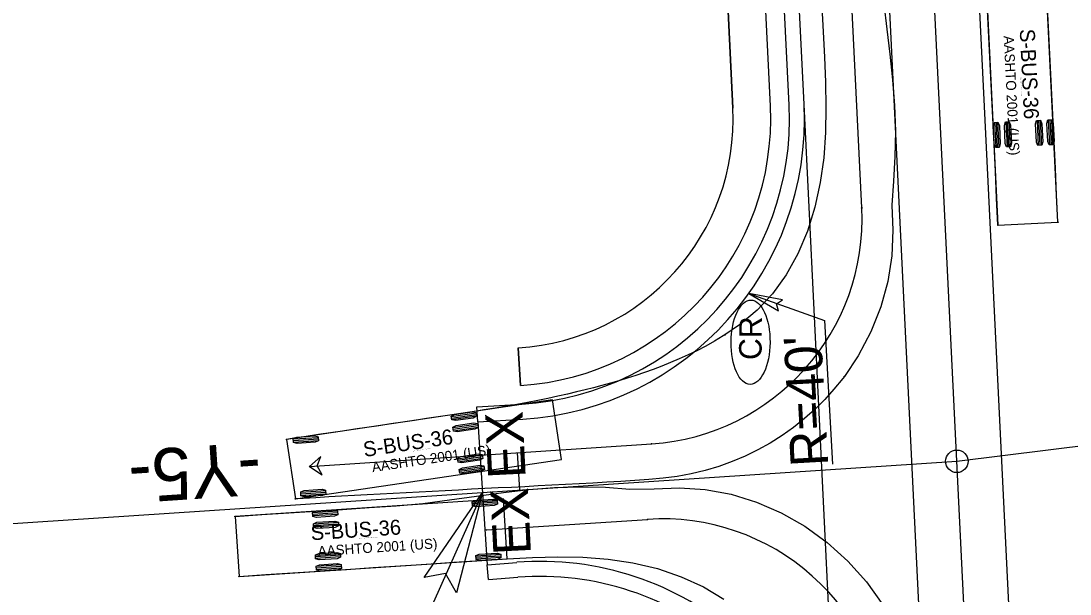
# Model space of a CAD drawing. Extents: x 2367848 to 2369479, y 800728 to 808616.
# Drawn here: x 2368698.2 to 2368837.9, y 804048.8 to 804125 of the extents above; entities that cross this region are included whole.
import ezdxf

# ---------------------------------------------------------------- set-up
doc = ezdxf.new("R2010")
doc.units = 0
for name, color, linetype in [('Prop AutoTurn Projected Path', 7, 'Continuous'), ('Prop AutoTurn Simulation', 7, 'Continuous'), ('Prop Conc 2ft 6in Curb and Gutter', 7, 'Continuous'), ('Prop Conc 4in Sidewalk', 7, 'Continuous'), ('Prop Dimension', 7, 'Continuous'), ('Prop EOT', 7, 'Continuous'), ('Prop Horizontal Alignment', 7, 'Continuous'), ('Prop Horizontal Alignment Station Label', 7, 'Continuous'), ('Prop Horizontal Alignment Tick Small', 7, 'Continuous'), ('Prop Lane Lines', 7, 'Continuous'), ('Prop Shade Light', 7, 'Continuous'), ('Prop Terminator CELL', 7, 'Continuous'), ('Prop WCC CELL', 7, 'Continuous'), ('Prop WCR CELL', 7, 'Continuous')]:
    doc.layers.add(name, color=color, linetype=linetype)

# ---------------------------------------------------------------- blocks, each defined once
blk = doc.blocks.new('CR')
at = {"layer": 'Prop WCC CELL'}
blk.add_ellipse((0.02, -0.02), major_axis=(5.61, 0), ratio=0.462467, dxfattribs=at)
blk.add_text('CR', height=3, dxfattribs=at).set_placement((-2.34, -1.5))

msp = doc.modelspace()

# ---------------------------------------------------------------- linework, layer by layer
at = {"layer": 'Prop AutoTurn Projected Path'}
for p, q in [((2368810.14, 804100.16), (2368808.54, 804132.96)), ((2368736.6, 804065.76), (2368782.15, 804068.76)), ((2368760.18, 804057.29), (2368781.62, 804058.7))]:
    msp.add_line(p, q, dxfattribs=at)
for centre, start, end in [((2368780.18, 804098.7), 273.7692, 2.7965), ((2368783.59, 804028.77), 2.7965, 93.7692)]:
    msp.add_arc(centre, 30, start, end, dxfattribs=at)
at = {"layer": 'Prop AutoTurn Simulation'}
for p, q in [((2368836.27, 804098.26), (2368834.52, 804134.02)), ((2368826.53, 804133.63), (2368828.28, 804097.87)), ((2368827.82, 804111.53), (2368827.98, 804108.2)), ((2368828.02, 804111.54), (2368828.19, 804108.21)), ((2368828.23, 804111.55), (2368828.4, 804108.22)), ((2368829.31, 804111.6), (2368829.48, 804108.28)), ((2368829.52, 804111.61), (2368829.69, 804108.29)), ((2368829.73, 804111.62), (2368829.89, 804108.3)), ((2368833.48, 804111.81), (2368833.64, 804108.48)), ((2368833.68, 804111.82), (2368833.85, 804108.49)), ((2368833.89, 804111.83), (2368834.06, 804108.5)), ((2368834.97, 804111.88), (2368835.14, 804108.55)), ((2368835.18, 804111.89), (2368835.35, 804108.56)), ((2368835.39, 804111.9), (2368835.55, 804108.57)), ((2368828.28, 804097.87), (2368836.27, 804098.26)), ((2368768.96, 804074.6), (2368733.54, 804069.35)), ((2368770.13, 804066.69), (2368768.96, 804074.6)), ((2368755.47, 804072.39), (2368758.77, 804072.88)), ((2368755.5, 804072.18), (2368758.8, 804072.67)), ((2368755.53, 804071.98), (2368758.83, 804072.47)), ((2368755.69, 804070.91), (2368758.99, 804071.4)), ((2368755.72, 804070.7), (2368759.02, 804071.19)), ((2368755.75, 804070.49), (2368759.05, 804070.98)), ((2368734.44, 804069.41), (2368737.76, 804069.62)), ((2368734.45, 804069.2), (2368737.78, 804069.42)), ((2368733.54, 804069.35), (2368734.72, 804061.44)), ((2368734.46, 804068.99), (2368737.79, 804069.21)), ((2368734.72, 804061.44), (2368770.13, 804066.69)), ((2368756.3, 804066.78), (2368759.6, 804067.27)), ((2368756.33, 804066.58), (2368759.63, 804067.07)), ((2368756.36, 804066.37), (2368759.66, 804066.86)), ((2368756.52, 804065.3), (2368759.82, 804065.79)), ((2368756.55, 804065.1), (2368759.85, 804065.58)), ((2368756.58, 804064.89), (2368759.88, 804065.38)), ((2368735.42, 804062.31), (2368738.75, 804062.53)), ((2368762.41, 804061.45), (2368726.69, 804059.09)), ((2368734.72, 804061.44), (2368734.72, 804061.44)), ((2368735.43, 804062.1), (2368738.76, 804062.32)), ((2368735.45, 804061.89), (2368738.77, 804062.11)), ((2368761.59, 804061.18), (2368758.26, 804060.96)), ((2368762.93, 804053.46), (2368762.41, 804061.45)), ((2368762.41, 804061.45), (2368762.41, 804061.45)), ((2368740.34, 804059.78), (2368737.01, 804059.56)), ((2368761.6, 804060.98), (2368758.28, 804060.76)), ((2368761.62, 804060.77), (2368758.29, 804060.55)), ((2368726.69, 804059.09), (2368727.21, 804051.11)), ((2368740.35, 804059.58), (2368737.02, 804059.36)), ((2368740.36, 804059.37), (2368737.04, 804059.15)), ((2368740.44, 804058.29), (2368737.11, 804058.07)), ((2368740.45, 804058.08), (2368737.12, 804057.86)), ((2368740.46, 804057.87), (2368737.14, 804057.65)), ((2368740.71, 804054.13), (2368737.38, 804053.91)), ((2368727.21, 804051.11), (2368762.93, 804053.46)), ((2368740.72, 804053.92), (2368737.4, 804053.7)), ((2368740.74, 804053.71), (2368737.41, 804053.49)), ((2368762.06, 804054.03), (2368758.74, 804053.81)), ((2368762.08, 804053.82), (2368758.75, 804053.61)), ((2368762.09, 804053.62), (2368758.76, 804053.4)), ((2368740.81, 804052.63), (2368737.48, 804052.41)), ((2368740.82, 804052.42), (2368737.5, 804052.21)), ((2368740.83, 804052.22), (2368737.51, 804052))]:
    msp.add_line(p, q, dxfattribs=at)
for points in [[(2368804.83, 804126.92), (2368804.99, 804123.58), (2368805.16, 804120.23), (2368805.3, 804116.88), (2368805.36, 804113.53), (2368805.3, 804110.18), (2368805.07, 804106.84), (2368804.62, 804103.52), (2368803.91, 804100.25), (2368802.91, 804097.05), (2368801.62, 804094.03), (2368800.05, 804091.25), (2368798.23, 804088.74), (2368796.19, 804086.56), (2368793.99, 804084.69), (2368791.92, 804083.26)], [(2368813.07, 804127.32), (2368813.48, 804123.97), (2368813.89, 804120.61), (2368814.25, 804117.21), (2368814.51, 804113.8), (2368814.62, 804110.39), (2368814.56, 804107.01), (2368814.35, 804103.73), (2368814.13, 804100.53), (2368814.28, 804097.19), (2368814.16, 804093.79), (2368813.62, 804090.36), (2368812.69, 804086.97), (2368811.36, 804083.65), (2368809.66, 804080.46), (2368807.82, 804077.74)], [(2368836.27, 804098.26), (2368836.09, 804101.84), (2368835.92, 804105.41), (2368835.74, 804108.99), (2368835.57, 804112.56), (2368835.39, 804116.14), (2368835.22, 804119.72), (2368835.04, 804123.29), (2368834.87, 804126.87)], [(2368828.28, 804097.87), (2368828.1, 804101.45), (2368827.93, 804105.02), (2368827.75, 804108.6), (2368827.58, 804112.17), (2368827.4, 804115.75), (2368827.23, 804119.33), (2368827.05, 804122.9), (2368826.88, 804126.48)], [(2368791.92, 804083.26), (2368791.69, 804083.11), (2368790.52, 804082.41), (2368789.35, 804081.75), (2368788.17, 804081.15), (2368787, 804080.58), (2368785.82, 804080.06), (2368784.66, 804079.56), (2368783.49, 804079.1), (2368782.34, 804078.66), (2368781.19, 804078.25), (2368780.04, 804077.87), (2368778.91, 804077.5), (2368777.78, 804077.16), (2368776.66, 804076.83), (2368775.54, 804076.52), (2368774.43, 804076.23), (2368773.32, 804075.94), (2368772.15, 804075.66), (2368770.93, 804075.37), (2368769.66, 804075.09), (2368768.35, 804074.81), (2368767.01, 804074.54), (2368765.62, 804074.27), (2368764.21, 804074.01), (2368762.77, 804073.75), (2368761.31, 804073.5), (2368759.82, 804073.26), (2368758.32, 804073.03), (2368756.79, 804072.8), (2368755.26, 804072.57), (2368753.71, 804072.34), (2368752.15, 804072.11), (2368750.58, 804071.88), (2368749, 804071.64), (2368747.41, 804071.41), (2368745.82, 804071.17), (2368744.22, 804070.93), (2368742.61, 804070.69), (2368741, 804070.46), (2368739.39, 804070.22), (2368737.77, 804069.98), (2368736.15, 804069.74), (2368734.52, 804069.49), (2368733.54, 804069.35)], [(2368807.82, 804077.74), (2368807.6, 804077.44), (2368806.44, 804076.01), (2368805.2, 804074.65), (2368803.89, 804073.34), (2368802.5, 804072.11), (2368801.04, 804070.95), (2368799.52, 804069.86), (2368797.93, 804068.86), (2368796.29, 804067.95), (2368794.6, 804067.12), (2368792.87, 804066.39), (2368791.09, 804065.75), (2368789.28, 804065.2), (2368787.44, 804064.76), (2368785.57, 804064.42), (2368783.69, 804064.18), (2368781.79, 804064.02), (2368779.91, 804063.89), (2368778.04, 804063.76), (2368776.18, 804063.65), (2368774.33, 804063.54), (2368772.5, 804063.43), (2368770.67, 804063.33), (2368768.86, 804063.24), (2368767.06, 804063.15), (2368765.26, 804063.05), (2368763.48, 804062.96), (2368761.7, 804062.88), (2368759.93, 804062.79), (2368758.17, 804062.7), (2368756.42, 804062.61), (2368754.67, 804062.52), (2368752.93, 804062.43), (2368751.19, 804062.34), (2368749.46, 804062.25), (2368747.73, 804062.16), (2368746.01, 804062.07), (2368744.29, 804061.97), (2368742.57, 804061.88), (2368740.86, 804061.78), (2368739.15, 804061.69), (2368737.44, 804061.59), (2368735.74, 804061.49), (2368734.72, 804061.44)], [(2368726.69, 804059.09), (2368730.26, 804059.33), (2368733.83, 804059.56), (2368737.4, 804059.8), (2368740.97, 804060.03), (2368744.55, 804060.27), (2368748.12, 804060.51), (2368751.69, 804060.83), (2368755.25, 804061.3), (2368758.82, 804061.78), (2368762.42, 804062.29), (2368762.42, 804062.29), (2368765.82, 804062.67), (2368769.24, 804062.93), (2368772.66, 804063.03), (2368776.01, 804062.97), (2368779.24, 804062.74), (2368782.51, 804062.77), (2368785.88, 804062.92), (2368789.3, 804062.69), (2368792.73, 804062.05), (2368796.12, 804061.01), (2368799.42, 804059.59), (2368802.57, 804057.79), (2368805.54, 804055.64), (2368808.29, 804053.16), (2368810.76, 804050.38), (2368812.93, 804047.34)], [(2368727.21, 804051.11), (2368730.78, 804051.35), (2368734.36, 804051.58), (2368737.93, 804051.82), (2368741.5, 804052.05), (2368745.07, 804052.29), (2368748.65, 804052.52), (2368752.22, 804052.76), (2368755.79, 804052.99), (2368759.36, 804053.23), (2368762.93, 804053.46), (2368762.93, 804053.46), (2368762.93, 804053.46), (2368766.29, 804053.64), (2368769.64, 804053.72), (2368773, 804053.65), (2368776.35, 804053.39), (2368779.67, 804052.9), (2368782.93, 804052.14), (2368786.09, 804051.07), (2368789.05, 804049.71), (2368791.75, 804048.08)]]:
    msp.add_lwpolyline(points, dxfattribs=at)
for points in [[(2368827.76, 804111.53), (2368828.28, 804111.55), (2368828.46, 804111.1), (2368828.58, 804108.7), (2368828.45, 804108.22), (2368827.93, 804108.2), (2368827.75, 804108.66), (2368827.63, 804111.05)], [(2368829.26, 804111.6), (2368829.78, 804111.63), (2368829.96, 804111.17), (2368830.08, 804108.77), (2368829.95, 804108.3), (2368829.43, 804108.27), (2368829.25, 804108.73), (2368829.13, 804111.13)], [(2368833.42, 804111.81), (2368833.94, 804111.83), (2368834.12, 804111.37), (2368834.24, 804108.97), (2368834.11, 804108.5), (2368833.59, 804108.48), (2368833.41, 804108.93), (2368833.29, 804111.33)], [(2368834.92, 804111.88), (2368835.44, 804111.9), (2368835.62, 804111.45), (2368835.74, 804109.05), (2368835.6, 804108.57), (2368835.09, 804108.55), (2368834.91, 804109.01), (2368834.79, 804111.4)], [(2368755.54, 804071.93), (2368755.46, 804072.44), (2368755.9, 804072.66), (2368758.27, 804073.02), (2368758.76, 804072.93), (2368758.83, 804072.42), (2368758.4, 804072.19), (2368756.02, 804071.84)], [(2368755.76, 804070.44), (2368755.68, 804070.96), (2368756.12, 804071.18), (2368758.49, 804071.53), (2368758.98, 804071.45), (2368759.05, 804070.93), (2368758.62, 804070.71), (2368756.24, 804070.36)], [(2368734.47, 804068.94), (2368734.43, 804069.46), (2368734.89, 804069.65), (2368737.28, 804069.8), (2368737.76, 804069.68), (2368737.79, 804069.16), (2368737.34, 804068.97), (2368734.94, 804068.81)], [(2368736.6, 804065.76), (2368738.27, 804064.65), (2368737.6, 804065.83), (2368738.11, 804067.08)], [(2368756.37, 804066.32), (2368756.29, 804066.84), (2368756.73, 804067.06), (2368759.11, 804067.41), (2368759.59, 804067.33), (2368759.67, 804066.81), (2368759.23, 804066.59), (2368756.85, 804066.24)], [(2368756.59, 804064.84), (2368756.51, 804065.35), (2368756.95, 804065.58), (2368759.33, 804065.93), (2368759.81, 804065.84), (2368759.89, 804065.33), (2368759.45, 804065.1), (2368757.07, 804064.75)], [(2368735.45, 804061.84), (2368735.42, 804062.36), (2368735.87, 804062.55), (2368738.27, 804062.71), (2368738.74, 804062.58), (2368738.78, 804062.06), (2368738.32, 804061.88), (2368735.93, 804061.72)], [(2368761.59, 804061.24), (2368761.62, 804060.72), (2368761.17, 804060.53), (2368758.77, 804060.37), (2368758.29, 804060.5), (2368758.26, 804061.02), (2368758.72, 804061.2), (2368761.11, 804061.36)], [(2368740.33, 804059.84), (2368740.37, 804059.32), (2368739.91, 804059.13), (2368737.52, 804058.97), (2368737.04, 804059.1), (2368737.01, 804059.62), (2368737.46, 804059.8), (2368739.86, 804059.96)], [(2368740.43, 804058.34), (2368740.47, 804057.82), (2368740.01, 804057.63), (2368737.62, 804057.47), (2368737.14, 804057.6), (2368737.11, 804058.12), (2368737.56, 804058.31), (2368739.96, 804058.46)], [(2368740.71, 804054.18), (2368740.74, 804053.66), (2368740.28, 804053.47), (2368737.89, 804053.32), (2368737.41, 804053.44), (2368737.38, 804053.96), (2368737.83, 804054.15), (2368740.23, 804054.31)], [(2368762.06, 804054.08), (2368762.09, 804053.57), (2368761.64, 804053.38), (2368759.24, 804053.22), (2368758.77, 804053.35), (2368758.73, 804053.87), (2368759.19, 804054.05), (2368761.58, 804054.21)], [(2368740.8, 804052.68), (2368740.84, 804052.17), (2368740.38, 804051.98), (2368737.99, 804051.82), (2368737.51, 804051.95), (2368737.48, 804052.46), (2368737.93, 804052.65), (2368740.33, 804052.81)]]:
    msp.add_lwpolyline(points, close=True, dxfattribs=at)
for centre in [(2368810.14, 804100.16), (2368810.14, 804100.16), (2368828.28, 804097.87), (2368836.27, 804098.26), (2368791.92, 804083.26), (2368791.92, 804083.26), (2368807.82, 804077.74), (2368807.82, 804077.74), (2368733.54, 804069.35), (2368782.15, 804068.76), (2368782.15, 804068.76), (2368736.6, 804065.76), (2368734.72, 804061.44), (2368726.69, 804059.09), (2368781.62, 804058.7), (2368781.62, 804058.7), (2368760.18, 804057.29), (2368727.21, 804051.11)]:
    msp.add_circle(centre, 0.0417, dxfattribs=at)
at = {"layer": 'Prop Conc 2ft 6in Curb and Gutter'}
for p, q in [((2368800.46, 804113.82), (2368788.23, 804364.22)), ((2368758.87, 804073.67), (2368764.86, 804074.04)), ((2368759, 804071.67), (2368758.87, 804073.67)), ((2368760.41, 804050.68), (2368760.25, 804052.67)), ((2368760.41, 804050.68), (2368764.34, 804050.99))]:
    msp.add_line(p, q, dxfattribs=at)
for centre, start, end in [((2368762.51, 804111.97), 273.5435, 2.7965), ((2368767.34, 804013.11), 2.7965, 94.5299)]:
    msp.add_arc(centre, 38, start, end, dxfattribs=at)
at = {"layer": 'Prop Conc 4in Sidewalk'}
for p, q in [((2368792.97, 804113.45), (2368780.55, 804367.68)), ((2368797.97, 804113.7), (2368785.59, 804367.05)), ((2368764.7, 804076.53), (2368764.39, 804081.53))]:
    msp.add_line(p, q, dxfattribs=at)
for radius in [30.5, 35.5]:
    msp.add_arc((2368762.51, 804111.97), radius, 273.5435, 2.7965, dxfattribs=at)
at = {"layer": 'Prop Dimension'}
for p, q in [((2368795.09, 804088.77), (2368805.17, 804085.17)), ((2368805.17, 804085.17), (2368806.24, 804066.04)), ((2368759.62, 804062.26), (2368706.24, 803943.3))]:
    msp.add_line(p, q, dxfattribs=at)
at = {"layer": 'Prop EOT'}
for p, q in [((2368802.46, 804113.92), (2368775.2, 804671.91)), ((2368759, 804071.67), (2368764.98, 804072.04)), ((2368759, 804071.67), (2368760.25, 804052.67)), ((2368760.25, 804052.67), (2368764.18, 804052.98))]:
    msp.add_line(p, q, dxfattribs=at)
for centre, start, end in [((2368762.51, 804111.97), 273.5435, 2.7965), ((2368767.34, 804013.11), 2.7965, 94.5299)]:
    msp.add_arc(centre, 40, start, end, dxfattribs=at)
at = {"layer": 'Prop Horizontal Alignment'}
for p, q in [((2368838.03, 803754.72), (2368793.18, 804672.79)), ((2368565.04, 804049.45), (2368822.8, 804066.43))]:
    msp.add_line(p, q, dxfattribs=at)
at = {"layer": 'Prop Horizontal Alignment Station Label'}
msp.add_line((2368822.8, 804066.43), (2368916.01, 804078.02), dxfattribs=at)
msp.add_circle((2368822.8, 804066.43), 1.5, dxfattribs=at)
at = {"layer": 'Prop Horizontal Alignment Tick Small'}
msp.add_line((2368764.6, 804062.59), (2368764.28, 804067.58), dxfattribs=at)
at = {"layer": 'Prop Lane Lines'}
for p, q in [((2368844.02, 803755.01), (2368799.18, 804673.08)), ((2368832.04, 803754.43), (2368787.19, 804672.49)), ((2368807.29, 804015.06), (2368802.46, 804113.92))]:
    msp.add_line(p, q, dxfattribs=at)
at = {"layer": 'Prop Shade Light'}
for p, q in [((2368797.97, 804113.7), (2368785.59, 804367.05)), ((2368780.59, 804366.85), (2368792.97, 804113.45)), ((2368764.39, 804081.53), (2368764.7, 804076.53))]:
    msp.add_line(p, q, dxfattribs=at)
for radius in [30.5, 35.5]:
    msp.add_arc((2368762.51, 804111.97), radius, 273.5435, 2.7965, dxfattribs=at)
at = {"layer": 'Prop Terminator CELL'}
for points in [[(2368799.58, 804087.92), (2368795.09, 804088.77), (2368799.06, 804086.44), (2368798.8, 804087.39)], [(2368751.88, 804050.96), (2368759.62, 804062.26), (2368756.15, 804048.92), (2368754.68, 804051.49)]]:
    msp.add_lwpolyline(points, close=True, dxfattribs=at)

# ---------------------------------------------------------------- block references
at = {"layer": 'Prop WCR CELL', "rotation": 89.41718587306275}
msp.add_blockref('CR', (2368795.31, 804082.26), dxfattribs=at)

# ---------------------------------------------------------------- texts
at = {"layer": 'Prop AutoTurn Simulation'}
for s, height, rotation, p in [('AASHTO 2001 (US)', 1.3333, 272.7965, (2368829.04, 804123.05)), ('S-BUS-36', 2, 272.7965, (2368831.17, 804123.94)), ('(c) 2014 Transoft Solutions, Inc. All rights reserved.', 0.08, 272.7965, (2368831.28, 804117.57)), ('S-BUS-36', 2, 8.4355, (2368743.9, 804067)), ('AASHTO 2001 (US)', 1.3333, 8.4355, (2368745, 804064.98)), ('(c) 2014 Transoft Solutions, Inc. All rights reserved.', 0.08, 8.4355, (2368750.23, 804067.74)), ('S-BUS-36', 2, 3.7692, (2368736.82, 804055.91)), ('AASHTO 2001 (US)', 1.3333, 3.7692, (2368737.74, 804053.8)), ('(c) 2014 Transoft Solutions, Inc. All rights reserved.', 0.08, 3.7692, (2368743.19, 804056.13))]:
    msp.add_text(s, height=height, rotation=rotation, dxfattribs=at).set_placement(p)
at = {"layer": 'Prop Dimension'}
for s, rotation, p in [("R=40'", 93.2028, (2368805.69, 804065.86)), ('EX', 92.7929, (2368765.39, 804064.25)), ('EX', 92.7929, (2368766.09, 804054.09))]:
    msp.add_text(s, height=5, rotation=rotation, dxfattribs=at).set_placement(p)
at = {"layer": 'Prop Horizontal Alignment Station Label'}
msp.add_text('-Y5-', height=7, rotation=183.7692, dxfattribs=at).set_placement((2368729.93, 804068.99))

doc.saveas('drawing.dxf')
